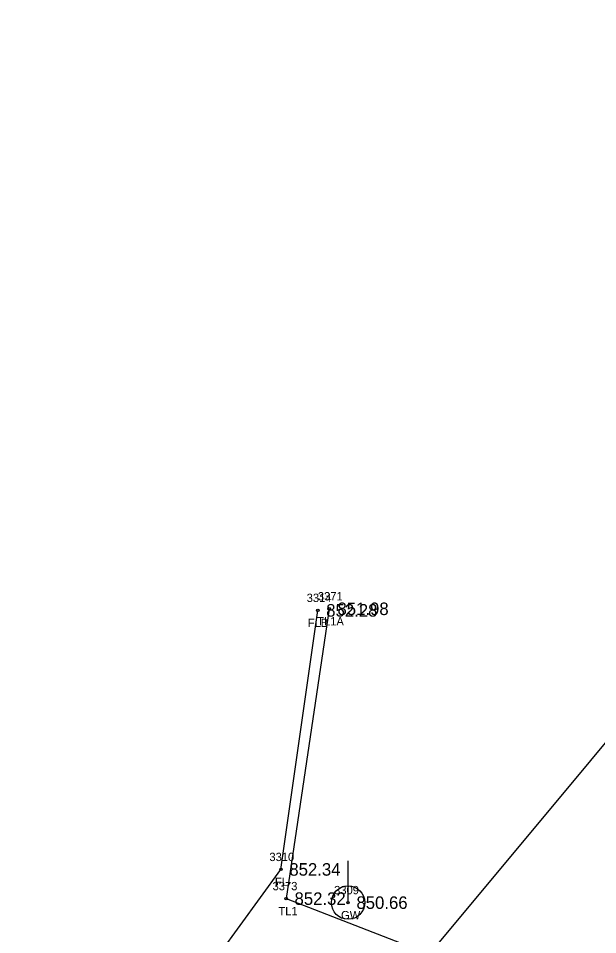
# Model space of a CAD drawing. Extents: x 1622501 to 1626664, y 1117816 to 1121579.
# Drawn here: x 1624132.8 to 1624202.2, y 1119531.1 to 1119640.9 of the extents above; entities that cross this region are included whole.
import ezdxf

# ---------------------------------------------------------------- set-up
doc = ezdxf.new("R2010")
doc.units = 0
for name, color, linetype in [('RD_EX_Fence_Other', 7, 'Continuous'), ('RD_EX_Fence_Other_txCode', 7, 'Continuous'), ('RD_EX_TX_Fence_Other_ELEV', 7, 'Continuous'), ('RD_EX_TX_UT_ELEV', 7, 'Continuous'), ('RD_EX_TX_VEG_ELEV', 7, 'Continuous'), ('RD_EX_UT', 7, 'Continuous'), ('RD_EX_UT_txCode', 7, 'Continuous'), ('RD_EX_VEG', 7, 'Continuous'), ('RD_EX_VEG_txCode', 7, 'Continuous'), ('RD_SMD_Locator', 7, 'Continuous')]:
    doc.layers.add(name, color=color, linetype=linetype)

msp = doc.modelspace()

# ---------------------------------------------------------------- linework, layer by layer
at = {"layer": 'RD_EX_Fence_Other'}
msp.add_lwpolyline([(1623864.47, 1119305.23), (1623867.28, 1119298.71), (1623872.01, 1119286.87), (1623881.85, 1119265.91), (1623912.38, 1119292.89), (1623945.47, 1119322.13), (1623989.37, 1119361.05), (1624030.89, 1119397.86), (1624061.41, 1119424.93), (1624104.3, 1119463.41), (1624135.03, 1119498.68), (1624164.28, 1119538.95), (1624168.7, 1119569.99)], dxfattribs=at)
at = {"layer": 'RD_EX_UT'}
msp.add_line((1624172.32, 1119534.97), (1624172.32, 1119539.97), dxfattribs=at)
msp.add_circle((1624172.32, 1119534.97), 2, dxfattribs=at)
at = {"layer": 'RD_EX_VEG'}
msp.add_lwpolyline([(1624170.05, 1119570.18), (1624164.9, 1119535.45), (1624182.09, 1119528.79), (1624240.28, 1119598.64), (1624220.35, 1119640.93)], dxfattribs=at)
at = {"layer": 'RD_SMD_Locator'}
for centre in [(1624168.7, 1119569.99), (1624170.05, 1119570.18), (1624164.28, 1119538.95), (1624164.9, 1119535.45), (1624172.32, 1119534.97)]:
    msp.add_circle(centre, 0.15, dxfattribs=at)

# ---------------------------------------------------------------- texts
at = {"layer": 'RD_EX_Fence_Other_txCode'}
for s, p in [('3314', (1624167.36, 1119570.99)), ('FLB', (1624167.5, 1119567.99)), ('3310', (1624162.89, 1119539.95)), ('FL', (1624163.55, 1119536.95))]:
    msp.add_text(s, height=1, dxfattribs=at).set_placement(p)
at = {"layer": 'RD_EX_TX_Fence_Other_ELEV'}
for s, p in [('852.28', (1624169.7, 1119569.24)), ('852.34', (1624165.28, 1119538.2))]:
    msp.add_text(s, height=1.5, dxfattribs=at).set_placement(p)
at = {"layer": 'RD_EX_TX_UT_ELEV'}
msp.add_text('850.66', height=1.5, dxfattribs=at).set_placement((1624173.32, 1119534.22))
at = {"layer": 'RD_EX_TX_VEG_ELEV'}
for s, p in [('851.98', (1624171.05, 1119569.43)), ('852.32', (1624165.9, 1119534.7))]:
    msp.add_text(s, height=1.5, dxfattribs=at).set_placement(p)
at = {"layer": 'RD_EX_UT_txCode'}
for s, p in [('3309', (1624170.65, 1119535.97)), ('GW', (1624171.48, 1119532.97))]:
    msp.add_text(s, height=1, dxfattribs=at).set_placement(p)
at = {"layer": 'RD_EX_VEG_txCode'}
for s, p in [('3371', (1624168.7, 1119571.18)), ('TL1A', (1624168.62, 1119568.18)), ('3373', (1624163.27, 1119536.45)), ('TL1', (1624163.97, 1119533.45))]:
    msp.add_text(s, height=1, dxfattribs=at).set_placement(p)

doc.saveas('drawing.dxf')
